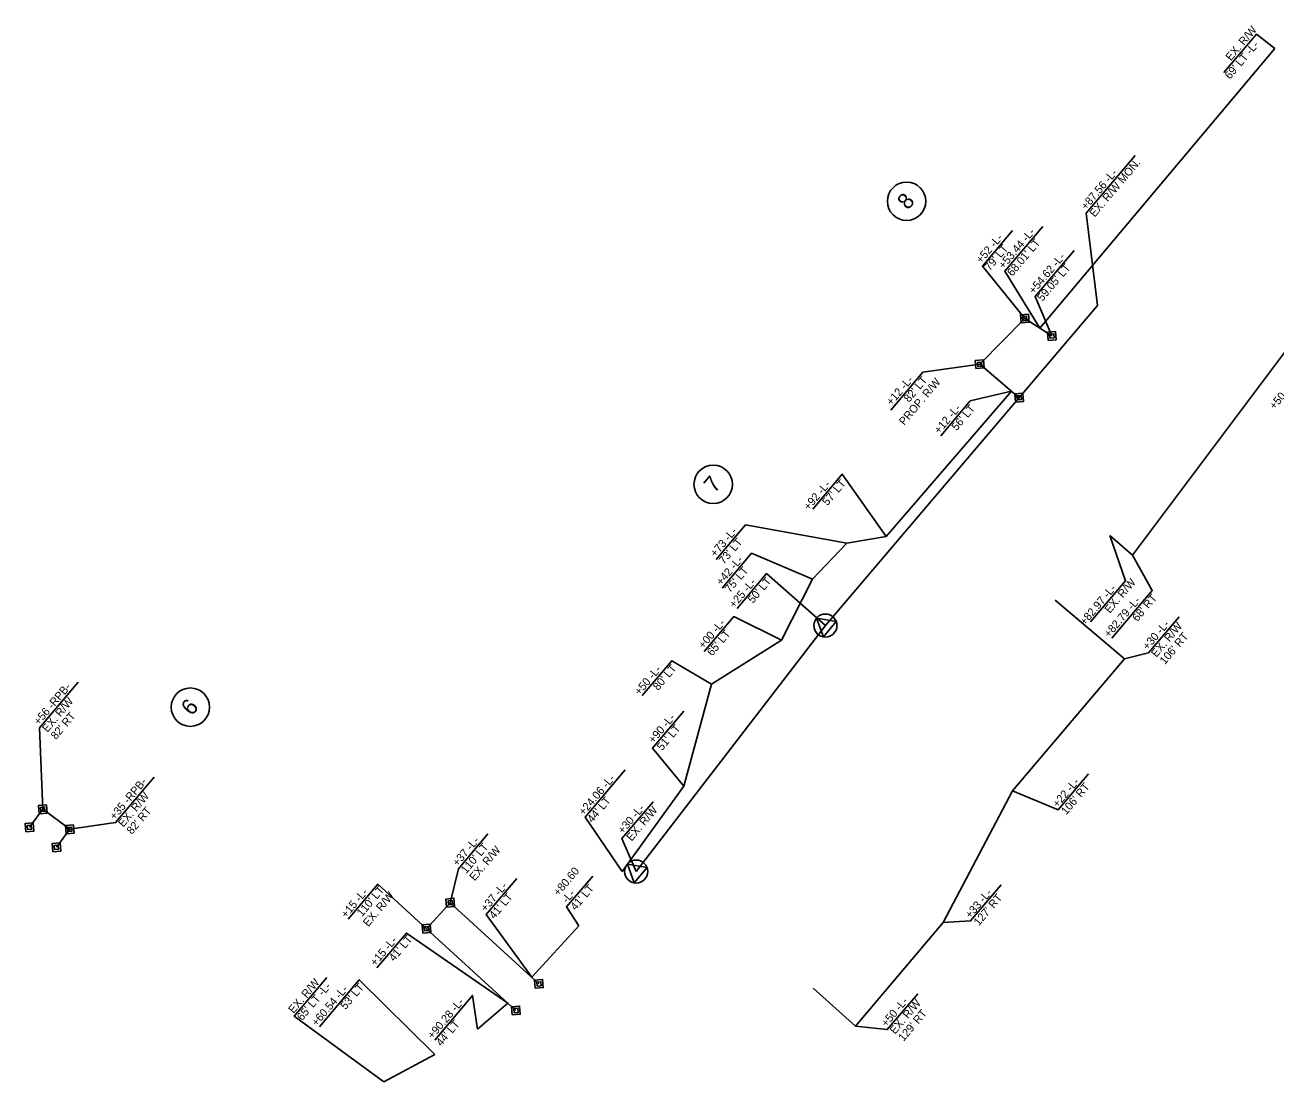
# Model space of a CAD drawing. Extents: x 1761749 to 1764136, y 422439 to 425054.
# Drawn here: x 1762517 to 1763299, y 423737 to 424397 of the extents above; entities that cross this region are included whole.
import ezdxf

# ---------------------------------------------------------------- set-up
doc = ezdxf.new("R2010")
doc.units = 0
for name, color, linetype in [('Prop Easement Construction', 7, 'Continuous'), ('Prop Easement Construction Station Offsets', 7, 'Continuous'), ('Prop Easement Permanent Drainage', 7, 'Continuous'), ('Prop Easement Permanent Drainage Station Offsets', 7, 'Continuous'), ('Prop Parcel Number CELL', 7, 'Continuous'), ('Prop Parcel Number Text', 7, 'Continuous'), ('Prop ROW Marker CELL', 7, 'Continuous'), ('Prop ROW Permanent Easement CELL', 7, 'Continuous'), ('Prop ROW RW Lines', 7, 'Continuous'), ('Prop ROW Station Offsets', 7, 'Continuous')]:
    doc.layers.add(name, color=color, linetype=linetype)

msp = doc.modelspace()

# ---------------------------------------------------------------- linework, layer by layer
at = {"layer": 'Prop Easement Construction'}
for p, q in [((1763151.28, 424207.73), (1763298.13, 424382.61)), ((1763209.39, 424065.91), (1763309.84, 424199.96)), ((1763055.33, 424077.43), (1763133.66, 424168.35)), ((1763009.27, 424050.92), (1763030.84, 424073.28)), ((1763030.84, 424073.28), (1763055.33, 424077.43)), ((1763195.17, 424078.2), (1763209.39, 424065.91)), ((1762989.92, 424012.74), (1763009.27, 424050.92)), ((1763160.93, 424037.78), (1763204.26, 424001.07)), ((1762946.27, 423985.17), (1762989.92, 424012.74)), ((1763134.31, 423918.52), (1763204.26, 424001.07)), ((1762928.84, 423921.46), (1762946.27, 423985.17)), ((1762890.31, 423868.13), (1762928.84, 423921.46)), ((1763090.92, 423836.12), (1763134.31, 423918.52)), ((1762833.87, 423801.99), (1762863.31, 423834.14)), ((1763036.11, 423771.42), (1763090.92, 423836.12)), ((1763009.69, 423795.23), (1763036.11, 423771.42)), ((1762800.11, 423769.55), (1762819.01, 423785.76)), ((1762741.52, 423736.54), (1762773.39, 423753.69))]:
    msp.add_line(p, q, dxfattribs=at)
at = {"layer": 'Prop Easement Construction Station Offsets'}
for points in [[(1763298.13, 424382.61), (1763286.79, 424391.54), (1763266.38, 424367.45)], [(1763151.28, 424207.73), (1763129.45, 424243.29), (1763153.18, 424271.3)], [(1763133.66, 424168.35), (1763107.92, 424162.27), (1763089.47, 424140.5)], [(1763055.33, 424077.43), (1763027.94, 424116.46), (1763009.48, 424094.68)], [(1763030.84, 424073.28), (1762967.54, 424084.8), (1762949.09, 424063.02)], [(1763182.98, 424024.09), (1763204.83, 424049.88), (1763195.17, 424078.2)], [(1763009.27, 424050.92), (1762971.25, 424067.03), (1762952.8, 424045.25)], [(1763196.38, 424013.87), (1763221.64, 424043.69), (1763209.39, 424065.91)], [(1762989.92, 424012.74), (1762960.13, 424027.47), (1762941.68, 424005.69)], [(1763204.26, 424001.07), (1763219.34, 424004.86), (1763238.37, 424027.32)], [(1762946.27, 423985.17), (1762921.41, 423999.88), (1762902.96, 423978.1)], [(1762928.84, 423921.46), (1762909.29, 423945.21), (1762928.87, 423968.33)], [(1762890.31, 423868.13), (1762867.29, 423902.02), (1762892.33, 423931.57)], [(1763134.31, 423918.52), (1763162.75, 423906.6), (1763181.78, 423929.07)], [(1762833.87, 423801.99), (1762805.48, 423841.18), (1762824.53, 423863.66)], [(1762863.31, 423834.14), (1762855.6, 423845.92), (1762871.99, 423865.26)], [(1763090.92, 423836.12), (1763108.16, 423837.26), (1763127.19, 423859.72)], [(1762819.01, 423785.76), (1762755.57, 423829.61), (1762737.12, 423807.83)], [(1762741.52, 423736.54), (1762685.44, 423777.71), (1762705.8, 423801.75)], [(1762773.39, 423753.69), (1762726.08, 423800.47), (1762701.19, 423771.09)], [(1763036.11, 423771.42), (1763056.02, 423769.27), (1763075.05, 423791.73)], [(1762800.11, 423769.55), (1762796.96, 423790.62), (1762773.32, 423762.71)]]:
    msp.add_lwpolyline(points, dxfattribs=at)
at = {"layer": 'Prop Easement Permanent Drainage'}
for p, q in [((1763113.82, 424185.16), (1763141.96, 424213.74)), ((1763141.96, 424213.74), (1763158.88, 424202.84)), ((1763113.82, 424185.16), (1763138.47, 424164.27)), ((1762520.02, 423895.72), (1762528.35, 423906.97)), ((1762528.35, 423906.97), (1762545.23, 423894.48)), ((1762536.9, 423883.22), (1762545.23, 423894.48)), ((1762768.12, 423832.35), (1762782.98, 423848.58)), ((1762782.98, 423848.58), (1762838.39, 423797.85)), ((1762768.12, 423832.35), (1762823.99, 423781.2))]:
    msp.add_line(p, q, dxfattribs=at)
at = {"layer": 'Prop Easement Permanent Drainage Station Offsets'}
for points in [[(1763141.96, 424213.74), (1763115.48, 424246.49), (1763134.28, 424268.68)], [(1763158.88, 424202.84), (1763148.41, 424227.41), (1763172.94, 424256.36)], [(1763113.82, 424185.16), (1763078.31, 424180.28), (1763058.19, 424156.53)], [(1762528.35, 423906.97), (1762526.42, 423957.94), (1762550.49, 423986.36)], [(1762545.23, 423894.48), (1762573.81, 423898.7), (1762597.89, 423927.12)], [(1762782.98, 423848.58), (1762788.1, 423869.8), (1762806.55, 423891.57)], [(1762768.12, 423832.35), (1762737.69, 423860.18), (1762719.24, 423838.4)]]:
    msp.add_lwpolyline(points, dxfattribs=at)
at = {"layer": 'Prop Parcel Number CELL'}
for p, q in [((1763068.12, 424287.04), (1763068.12, 424287.04)), ((1762947.28, 424110.09), (1762947.28, 424110.09)), ((1762620.6, 423970.83), (1762620.6, 423970.83))]:
    msp.add_line(p, q, dxfattribs=at)
for centre in [(1763068.12, 424287.04), (1762947.28, 424110.09), (1762620.6, 423970.83)]:
    msp.add_circle(centre, 12, dxfattribs=at)
at = {"layer": 'Prop ROW Marker CELL'}
for p, q in [((1763017.4, 424021.84), (1763017.4, 424021.84)), ((1762899.14, 423868.08), (1762899.14, 423868.08))]:
    msp.add_line(p, q, dxfattribs=at)
for points in [[(1763016.11, 424014.75), (1763011.9, 424026.5), (1763024.19, 424024.29)], [(1762897.85, 423860.99), (1762893.64, 423872.74), (1762905.93, 423870.53)]]:
    msp.add_lwpolyline(points, close=True, dxfattribs=at)
for centre in [(1763017.4, 424021.84), (1762899.14, 423868.08)]:
    msp.add_circle(centre, 7.2, dxfattribs=at)
at = {"layer": 'Prop ROW Permanent Easement CELL'}
for p, q in [((1763141.96, 424213.74), (1763141.96, 424213.74)), ((1763158.88, 424202.84), (1763158.88, 424202.84)), ((1763113.82, 424185.16), (1763113.82, 424185.16)), ((1763138.47, 424164.27), (1763138.47, 424164.27)), ((1762528.35, 423906.97), (1762528.35, 423906.97)), ((1762520.02, 423895.72), (1762520.02, 423895.72)), ((1762545.23, 423894.48), (1762545.23, 423894.48)), ((1762536.9, 423883.22), (1762536.9, 423883.22)), ((1762782.98, 423848.58), (1762782.98, 423848.58)), ((1762768.12, 423832.35), (1762768.12, 423832.35)), ((1762838.39, 423797.85), (1762838.39, 423797.85)), ((1762823.99, 423781.2), (1762823.99, 423781.2))]:
    msp.add_line(p, q, dxfattribs=at)
for points in [[(1763139.64, 424210.99), (1763139.22, 424216.06), (1763144.29, 424216.48), (1763144.71, 424211.41)], [(1763140.8, 424212.36), (1763140.59, 424214.9), (1763143.13, 424215.11), (1763143.34, 424212.57)], [(1763156.55, 424200.09), (1763156.13, 424205.17), (1763161.2, 424205.59), (1763161.62, 424200.51)], [(1763157.71, 424201.47), (1763157.5, 424204), (1763160.04, 424204.21), (1763160.25, 424201.68)], [(1763111.49, 424182.41), (1763111.07, 424187.48), (1763116.14, 424187.9), (1763116.56, 424182.83)], [(1763112.65, 424183.78), (1763112.44, 424186.32), (1763114.98, 424186.53), (1763115.19, 424183.99)], [(1763136.14, 424161.53), (1763135.72, 424166.6), (1763140.79, 424167.02), (1763141.21, 424161.95)], [(1763137.3, 424162.9), (1763137.09, 424165.44), (1763139.63, 424165.65), (1763139.84, 424163.11)], [(1762526.02, 423904.22), (1762525.6, 423909.3), (1762530.67, 423909.72), (1762531.09, 423904.64)], [(1762527.18, 423905.6), (1762526.97, 423908.13), (1762529.51, 423908.34), (1762529.72, 423905.81)], [(1762517.69, 423892.97), (1762517.27, 423898.04), (1762522.34, 423898.46), (1762522.76, 423893.39)], [(1762518.85, 423894.34), (1762518.64, 423896.88), (1762521.18, 423897.09), (1762521.39, 423894.55)], [(1762542.9, 423891.73), (1762542.48, 423896.8), (1762547.55, 423897.22), (1762547.97, 423892.15)], [(1762544.06, 423893.1), (1762543.85, 423895.64), (1762546.39, 423895.85), (1762546.6, 423893.31)], [(1762534.57, 423880.48), (1762534.15, 423885.55), (1762539.22, 423885.97), (1762539.64, 423880.9)], [(1762535.73, 423881.85), (1762535.52, 423884.39), (1762538.06, 423884.6), (1762538.27, 423882.06)], [(1762780.65, 423845.83), (1762780.23, 423850.91), (1762785.31, 423851.33), (1762785.73, 423846.25)], [(1762781.82, 423847.21), (1762781.61, 423849.74), (1762784.14, 423849.95), (1762784.35, 423847.42)], [(1762765.8, 423829.61), (1762765.38, 423834.68), (1762770.45, 423835.1), (1762770.87, 423830.03)], [(1762766.96, 423830.98), (1762766.75, 423833.52), (1762769.29, 423833.73), (1762769.5, 423831.19)], [(1762836.06, 423795.1), (1762835.64, 423800.18), (1762840.71, 423800.6), (1762841.13, 423795.52)], [(1762837.22, 423796.48), (1762837.01, 423799.01), (1762839.55, 423799.22), (1762839.76, 423796.69)], [(1762821.66, 423778.46), (1762821.24, 423783.53), (1762826.32, 423783.95), (1762826.74, 423778.88)], [(1762822.83, 423779.83), (1762822.62, 423782.37), (1762825.15, 423782.58), (1762825.36, 423780.04)]]:
    msp.add_lwpolyline(points, close=True, dxfattribs=at)
at = {"layer": 'Prop ROW RW Lines'}
for p, q in [((1763017.4, 424021.84), (1763187.4, 424221.85)), ((1762899.14, 423868.08), (1763017.4, 424021.84))]:
    msp.add_line(p, q, dxfattribs=at)
at = {"layer": 'Prop ROW Station Offsets'}
for points in [[(1763187.4, 424221.85), (1763180.35, 424279.54), (1763210.97, 424315.69)], [(1763017.4, 424021.84), (1762980.64, 424054.36), (1762962.19, 424032.59)], [(1762899.14, 423868.08), (1762890.22, 423888.63), (1762909.8, 423911.74)]]:
    msp.add_lwpolyline(points, dxfattribs=at)

# ---------------------------------------------------------------- texts
at = {"layer": 'Prop Easement Construction Station Offsets'}
for s, p in [('EX. R/W ', (1763270.74, 424374.43)), ("69' LT -L-", (1763270.17, 424362.92)), ('+53.44 -L-', (1763128.84, 424244.3)), ("68.01' LT", (1763134.19, 424239.78)), ('+50 -L-', (1763298.07, 424156.45)), ('+12 -L-', (1763088.55, 424141.25)), ("56' LT", (1763099.43, 424143.25)), ("57' LT", (1763018.68, 424096.43)), ('+92 -L-', (1763007.04, 424093.51)), ('+73 -L-', (1762948.7, 424064.28)), ("73' LT", (1762954.04, 424059.76)), ('+42 -L-', (1762952.41, 424046.51)), ("75' LT", (1762957.75, 424041.99)), ('EX. R/W', (1763195.13, 424029.11)), ('+82.97 -L-', (1763179.55, 424021.55)), ("68' RT", (1763212.39, 424023.97)), ('+82.79 -L-', (1763194.73, 424013.96)), ('+00 -L-', (1762941.29, 424006.96)), ("65' LT", (1762946.63, 424002.44)), ('+30 -L-', (1763218.86, 424006.17)), ('EX. R/W', (1763224.21, 424001.64)), ("106' RT", (1763229.55, 423997.12)), ('+50 -L-', (1762901.27, 423977.93)), ("80' LT", (1762912.92, 423980.86)), ('+90 -L-', (1762910.03, 423947.81)), ("51' LT", (1762915.37, 423943.29)), ('+24.06 -L-', (1762866.45, 423902.75)), ('+22 -L-', (1763162.57, 423907.67)), ("106' RT", (1763167.91, 423903.15)), ("44' LT", (1762871.79, 423898.22)), ('+80.60', (1762850.62, 423852.43)), ('+37 -L-', (1762805.2, 423842.57)), ("41' LT", (1762810.54, 423838.04)), ('-L-', (1762855.96, 423847.91)), ("41' LT", (1762861.3, 423843.38)), ('+33 -L-', (1763107.97, 423838.32)), ("127' RT", (1763113.31, 423833.8)), ('+15 -L-', (1762736.21, 423808.58)), ("41' LT", (1762747.86, 423811.5)), ('EX. R/W', (1762685.09, 423779.02)), ("65' LT -L-", (1762690.43, 423774.49)), ('+60.54 -L-', (1762699.56, 423770.99)), ("53' LT", (1762717.59, 423781.45)), ('+90.28 -L-', (1762772.05, 423763.05)), ('+50 -L-', (1763055.55, 423770.58)), ('EX. R/W', (1763060.89, 423766.05)), ("44' LT", (1762777.4, 423758.52)), ("129' RT", (1763066.24, 423761.53))]:
    msp.add_text(s, height=5, rotation=49.7301, dxfattribs=at).set_placement(p)
at = {"layer": 'Prop Easement Permanent Drainage Station Offsets'}
for s, p in [('+52 -L-', (1763114.75, 424247.76)), ("79' LT", (1763120.09, 424243.23)), ('+54.62 -L-', (1763147.68, 424228.67)), ("59.05' LT", (1763153.02, 424224.14)), ('+12 -L-', (1763058.78, 424158.98)), ('PROP. R/W', (1763066.67, 424146.63)), ("82' LT", (1763069.65, 424160.99)), ('+56 -RPB-', (1762525.95, 423959.25)), ('EX. R/W', (1762531.29, 423954.72)), ("82' RT", (1762536.63, 423950.2)), ('+35 -RPB-', (1762573.34, 423900.01)), ('EX. R/W', (1762578.68, 423895.48)), ("82' RT", (1762584.03, 423890.96)), ('+37 -L-', (1762787.56, 423870.9)), ("110' LT", (1762792.9, 423866.38)), ('EX. R/W', (1762798.24, 423861.86)), ('+15 -L-', (1762717.99, 423838.67)), ("110' LT", (1762727.86, 423839.49)), ('EX. R/W', (1762731.74, 423833.25))]:
    msp.add_text(s, height=5, rotation=49.7301, dxfattribs=at).set_placement(p)
at = {"layer": 'Prop Parcel Number Text'}
for s, p in [('8', (1763068.99, 424281.15)), ('7', (1762948.16, 424104.21)), ('6', (1762621.47, 423964.94))]:
    msp.add_text(s, height=10, rotation=49.7301, dxfattribs=at).set_placement(p)
at = {"layer": 'Prop ROW Station Offsets'}
for s, p in [('EX. R/W MON.', (1763185.68, 424276.74)), ('+87.56 -L-', (1763180.34, 424281.26)), ('+25 -L-', (1762960.5, 424032.42)), ("50' LT", (1762972.15, 424035.34)), ('+30 -L-', (1762890.96, 423891.23)), ('EX. R/W', (1762896.3, 423886.7))]:
    msp.add_text(s, height=5, rotation=49.7301, dxfattribs=at).set_placement(p)

doc.saveas('drawing.dxf')
